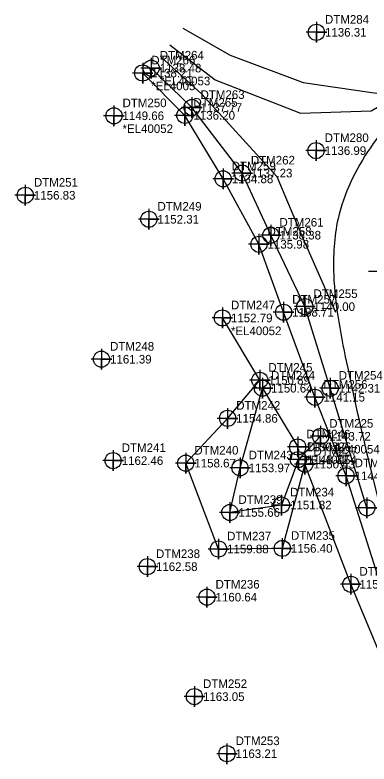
# Model space of a CAD drawing. Extents: x 1286409 to 1286829, y 857931 to 858308.
# Drawn here: x 1286408.7 to 1286511.7, y 857930.6 to 858148.3 of the extents above; entities that cross this region are included whole.
import ezdxf

# ---------------------------------------------------------------- set-up
doc = ezdxf.new("R2010")
doc.units = 0
for name, color, linetype in [('Exist DTM Breakline', 7, 'Continuous'), ('Exist DTM Breakline Cogo Comment', 7, 'Continuous'), ('Exist DTM Breakline Cogo Elevation', 7, 'Continuous'), ('Exist DTM Breakline Cogo Number', 7, 'Continuous'), ('Exist DTM Breakline Cogo Point CELL', 7, 'Continuous'), ('Exist DTM Crownline Cogo Point CELL', 7, 'Continuous'), ('Exist DTM Regular Point CELL', 7, 'Continuous'), ('Exist DTM Regular Point Cogo Elevation', 7, 'Continuous'), ('Exist DTM Regular Point Cogo Number', 7, 'Continuous'), ('Exist Roads EOP', 7, 'Continuous'), ('Exist Roads EOP Other', 7, 'Continuous'), ('Exist Roads Soil', 7, 'Continuous')]:
    doc.layers.add(name, color=color, linetype=linetype)

msp = doc.modelspace()

# ---------------------------------------------------------------- linework, layer by layer
at = {"layer": 'Exist DTM Breakline'}
for points in [[(1286520.872, 857956.475), (1286514.938, 857983.192), (1286504.975, 858014.397), (1286495.914, 858037.226), (1286486.828, 858061.942), (1286479.65, 858081.695), (1286469.24, 858100.695), (1286458.123, 858119.163), (1286445.852, 858131.468)], [(1286511.023, 858005.106), (1286500.357, 858039.834), (1286493.011, 858063.572), (1286483.119, 858084.338), (1286474.799, 858102.385), (1286460.172, 858121.45), (1286448.323, 858132.894)], [(1286517.862, 857955.312), (1286506.377, 857982.872), (1286493.003, 858017.794), (1286486.448, 857993.306), (1286467.899, 857993.131), (1286458.369, 858018.086), (1286470.547, 858031.105), (1286479.897, 858042.174), (1286469.015, 858060.288)], [(1286497.591, 858025.882), (1286491.129, 858019.112), (1286486.211, 858005.912), (1286471.196, 858003.751), (1286474.165, 858016.705), (1286480.661, 858039.856), (1286490.919, 858022.783)]]:
    msp.add_lwpolyline(points, dxfattribs=at)
at = {"layer": 'Exist DTM Breakline Cogo Point CELL'}
for points in [[(1286448.323, 858135.894), (1286448.323, 858129.894), (1286448.323, 858132.894), (1286451.323, 858132.894), (1286445.323, 858132.894)], [(1286445.852, 858134.468), (1286445.852, 858128.468), (1286445.852, 858131.468), (1286448.852, 858131.468), (1286442.852, 858131.468)], [(1286460.172, 858124.45), (1286460.172, 858118.45), (1286460.172, 858121.45), (1286463.172, 858121.45), (1286457.172, 858121.45)], [(1286437.488, 858122.042), (1286437.488, 858116.042), (1286437.488, 858119.042), (1286440.488, 858119.042), (1286434.488, 858119.042)], [(1286458.123, 858122.163), (1286458.123, 858116.163), (1286458.123, 858119.163), (1286461.123, 858119.163), (1286455.123, 858119.163)], [(1286474.799, 858105.385), (1286474.799, 858099.385), (1286474.799, 858102.385), (1286477.799, 858102.385), (1286471.799, 858102.385)], [(1286469.24, 858103.695), (1286469.24, 858097.695), (1286469.24, 858100.695), (1286472.24, 858100.695), (1286466.24, 858100.695)], [(1286447.653, 858091.967), (1286447.653, 858085.967), (1286447.653, 858088.967), (1286450.653, 858088.967), (1286444.653, 858088.967)], [(1286483.119, 858087.338), (1286483.119, 858081.338), (1286483.119, 858084.338), (1286486.119, 858084.338), (1286480.119, 858084.338)], [(1286479.65, 858084.695), (1286479.65, 858078.695), (1286479.65, 858081.695), (1286482.65, 858081.695), (1286476.65, 858081.695)], [(1286493.011, 858066.572), (1286493.011, 858060.572), (1286493.011, 858063.572), (1286496.011, 858063.572), (1286490.011, 858063.572)], [(1286486.828, 858064.942), (1286486.828, 858058.942), (1286486.828, 858061.942), (1286489.828, 858061.942), (1286483.828, 858061.942)], [(1286469.015, 858063.288), (1286469.015, 858057.288), (1286469.015, 858060.288), (1286472.015, 858060.288), (1286466.015, 858060.288)], [(1286479.897, 858045.174), (1286479.897, 858039.174), (1286479.897, 858042.174), (1286482.897, 858042.174), (1286476.897, 858042.174)], [(1286480.661, 858042.856), (1286480.661, 858036.856), (1286480.661, 858039.856), (1286483.661, 858039.856), (1286477.661, 858039.856)], [(1286500.357, 858042.834), (1286500.357, 858036.834), (1286500.357, 858039.834), (1286503.357, 858039.834), (1286497.357, 858039.834)], [(1286495.914, 858040.226), (1286495.914, 858034.226), (1286495.914, 858037.226), (1286498.914, 858037.226), (1286492.914, 858037.226)], [(1286470.547, 858034.105), (1286470.547, 858028.105), (1286470.547, 858031.105), (1286473.547, 858031.105), (1286467.547, 858031.105)], [(1286497.591, 858028.882), (1286497.591, 858022.882), (1286497.591, 858025.882), (1286500.591, 858025.882), (1286494.591, 858025.882)], [(1286490.919, 858025.783), (1286490.919, 858019.783), (1286490.919, 858022.783), (1286493.919, 858022.783), (1286487.919, 858022.783)], [(1286458.369, 858021.086), (1286458.369, 858015.086), (1286458.369, 858018.086), (1286461.369, 858018.086), (1286455.369, 858018.086)], [(1286491.129, 858022.112), (1286491.129, 858016.112), (1286491.129, 858019.112), (1286494.129, 858019.112), (1286488.129, 858019.112)], [(1286493.003, 858020.794), (1286493.003, 858014.794), (1286493.003, 858017.794), (1286496.003, 858017.794), (1286490.003, 858017.794)], [(1286474.165, 858019.705), (1286474.165, 858013.705), (1286474.165, 858016.705), (1286477.165, 858016.705), (1286471.165, 858016.705)], [(1286504.975, 858017.397), (1286504.975, 858011.397), (1286504.975, 858014.397), (1286507.975, 858014.397), (1286501.975, 858014.397)], [(1286486.211, 858008.912), (1286486.211, 858002.912), (1286486.211, 858005.912), (1286489.211, 858005.912), (1286483.211, 858005.912)], [(1286511.023, 858008.106), (1286511.023, 858002.106), (1286511.023, 858005.106), (1286514.023, 858005.106), (1286508.023, 858005.106)], [(1286471.196, 858006.751), (1286471.196, 858000.751), (1286471.196, 858003.751), (1286474.196, 858003.751), (1286468.196, 858003.751)], [(1286486.448, 857996.306), (1286486.448, 857990.306), (1286486.448, 857993.306), (1286489.448, 857993.306), (1286483.448, 857993.306)], [(1286467.899, 857996.131), (1286467.899, 857990.131), (1286467.899, 857993.131), (1286470.899, 857993.131), (1286464.899, 857993.131)], [(1286506.377, 857985.872), (1286506.377, 857979.872), (1286506.377, 857982.872), (1286509.377, 857982.872), (1286503.377, 857982.872)]]:
    msp.add_lwpolyline(points, dxfattribs=at)
for centre in [(1286445.852, 858131.468), (1286448.323, 858132.894), (1286460.172, 858121.45), (1286437.488, 858119.042), (1286458.123, 858119.163), (1286469.24, 858100.695), (1286474.799, 858102.385), (1286447.653, 858088.967), (1286483.119, 858084.338), (1286479.65, 858081.695), (1286493.011, 858063.572), (1286486.828, 858061.942), (1286469.015, 858060.288), (1286479.897, 858042.174), (1286480.661, 858039.856), (1286500.357, 858039.834), (1286495.914, 858037.226), (1286470.547, 858031.105), (1286497.591, 858025.882), (1286490.919, 858022.783), (1286458.369, 858018.086), (1286491.129, 858019.112), (1286474.165, 858016.705), (1286493.003, 858017.794), (1286504.975, 858014.397), (1286486.211, 858005.912), (1286511.023, 858005.106), (1286471.196, 858003.751), (1286467.899, 857993.131), (1286486.448, 857993.306), (1286506.377, 857982.872)]:
    msp.add_circle(centre, 2.344, dxfattribs=at)
at = {"layer": 'Exist DTM Crownline Cogo Point CELL'}
msp.add_lwpolyline([(1286514.506, 858076.789), (1286514.506, 858070.789), (1286514.506, 858073.789), (1286517.506, 858073.789), (1286511.506, 858073.789)], dxfattribs=at)
at = {"layer": 'Exist DTM Regular Point CELL'}
for points in [[(1286496.358, 858146.298), (1286496.358, 858140.298), (1286496.358, 858143.298), (1286499.358, 858143.298), (1286493.358, 858143.298)], [(1286496.256, 858111.914), (1286496.256, 858105.914), (1286496.256, 858108.914), (1286499.256, 858108.914), (1286493.256, 858108.914)], [(1286411.723, 858098.932), (1286411.723, 858092.932), (1286411.723, 858095.932), (1286414.723, 858095.932), (1286408.723, 858095.932)], [(1286433.866, 858051.289), (1286433.866, 858045.289), (1286433.866, 858048.289), (1286436.866, 858048.289), (1286430.866, 858048.289)], [(1286437.253, 858021.812), (1286437.253, 858015.812), (1286437.253, 858018.812), (1286440.253, 858018.812), (1286434.253, 858018.812)], [(1286447.217, 857991.003), (1286447.217, 857985.003), (1286447.217, 857988.003), (1286450.217, 857988.003), (1286444.217, 857988.003)], [(1286464.539, 857982.132), (1286464.539, 857976.132), (1286464.539, 857979.132), (1286467.539, 857979.132), (1286461.539, 857979.132)], [(1286460.892, 857953.227), (1286460.892, 857947.227), (1286460.892, 857950.227), (1286463.892, 857950.227), (1286457.892, 857950.227)], [(1286470.365, 857936.641), (1286470.365, 857930.641), (1286470.365, 857933.641), (1286473.365, 857933.641), (1286467.365, 857933.641)]]:
    msp.add_lwpolyline(points, dxfattribs=at)
for centre in [(1286496.358, 858143.298), (1286496.256, 858108.914), (1286411.723, 858095.932), (1286433.866, 858048.289), (1286437.253, 858018.812), (1286447.217, 857988.003), (1286464.539, 857979.132), (1286460.892, 857950.227), (1286470.365, 857933.641)]:
    msp.add_circle(centre, 2.344, dxfattribs=at)
at = {"layer": 'Exist Roads EOP'}
msp.add_spline([(1286554.506, 858138.221), (1286544.419, 858134.401), (1286528.832, 858126.933), (1286512.047, 858109.768), (1286502.652, 858089.088), (1286501.393, 858072.897), (1286505.471, 858045.649), (1286512.056, 858016.522), (1286519.805, 857984.681), (1286525.58, 857958.7)], degree=3, dxfattribs=at)
at = {"layer": 'Exist Roads EOP Other'}
for points in [[(1286457.489, 858144.476), (1286471.264, 858136.623), (1286492.557, 858128.739), (1286511.821, 858125.921), (1286519.606, 858124.807)], [(1286453.703, 858139.674), (1286466.954, 858129.445), (1286491.774, 858119.764), (1286512.279, 858120.499), (1286519.676, 858124.715)]]:
    msp.add_lwpolyline(points, dxfattribs=at)
at = {"layer": 'Exist Roads Soil'}
msp.add_lwpolyline([(1286451.264, 858136.048), (1286463.084, 858125.359), (1286484.836, 858101.378), (1286492.165, 858084.188), (1286501.894, 858062.005)], dxfattribs=at)

# ---------------------------------------------------------------- texts
at = {"layer": 'Exist DTM Breakline Cogo Comment'}
for s, p in [('*EL40053', (1286450.823, 858127.894)), ('*EL4005', (1286448.352, 858126.468)), ('*EL40052', (1286439.988, 858114.042)), ('*EL40052', (1286471.515, 858055.288)), ('*BL40054', (1286500.091, 858020.882)), ('*EL40054', (1286493.419, 858017.783))]:
    msp.add_text(s, height=2.5, dxfattribs=at).set_placement(p)
at = {"layer": 'Exist DTM Breakline Cogo Elevation'}
for s, p in [('1138.48', (1286450.823, 858131.644)), ('1138.21', (1286448.352, 858130.218)), ('1137.77', (1286462.672, 858120.2)), ('1149.66', (1286439.988, 858117.792)), ('1136.20', (1286460.623, 858117.913)), ('1137.23', (1286477.299, 858101.135)), ('1134.88', (1286471.74, 858099.445)), ('1152.31', (1286450.153, 858087.717)), ('1138.38', (1286485.619, 858083.088)), ('1135.98', (1286482.15, 858080.445)), ('1140.00', (1286495.511, 858062.322)), ('1152.79', (1286471.515, 858059.038)), ('1138.71', (1286489.328, 858060.692)), ('1150.89', (1286482.397, 858040.924)), ('1150.64', (1286483.161, 858038.606)), ('1142.31', (1286502.857, 858038.584)), ('1141.15', (1286498.414, 858035.976)), ('1154.86', (1286473.047, 858029.855)), ('1143.72', (1286500.091, 858024.632)), ('1150.17', (1286493.419, 858021.533)), ('1148.32', (1286493.629, 858017.862)), ('1158.67', (1286460.869, 858016.836)), ('1153.97', (1286476.665, 858015.455)), ('1150.43', (1286495.503, 858016.544)), ('1144.38', (1286507.475, 858013.147)), ('1151.82', (1286488.711, 858004.662)), ('1155.66', (1286473.696, 858002.501)), ('1159.88', (1286470.399, 857991.881)), ('1156.40', (1286488.948, 857992.056)), ('1154.95', (1286508.877, 857981.622))]:
    msp.add_text(s, height=2.5, dxfattribs=at).set_placement(p)
at = {"layer": 'Exist DTM Breakline Cogo Number'}
for s, p in [('DTM264', (1286450.823, 858135.394)), ('DTM266', (1286448.352, 858133.968)), ('DTM263', (1286462.672, 858123.95)), ('DTM250', (1286439.988, 858121.542)), ('DTM265', (1286460.623, 858121.663)), ('DTM262', (1286477.299, 858104.885)), ('DTM259', (1286471.74, 858103.195)), ('DTM249', (1286450.153, 858091.467)), ('DTM261', (1286485.619, 858086.838)), ('DTM258', (1286482.15, 858084.195)), ('DTM255', (1286495.511, 858066.072)), ('DTM257', (1286489.328, 858064.442)), ('DTM247', (1286471.515, 858062.788)), ('DTM245', (1286482.397, 858044.674)), ('DTM244', (1286483.161, 858042.356)), ('DTM254', (1286502.857, 858042.334)), ('DTM256', (1286498.414, 858039.726)), ('DTM242', (1286473.047, 858033.605)), ('DTM225', (1286500.091, 858028.382)), ('DTM246', (1286493.419, 858025.283)), ('DTM240', (1286460.869, 858020.586)), ('DTM226', (1286493.629, 858021.612)), ('DTM227', (1286495.503, 858020.294)), ('DTM243', (1286476.665, 858019.205)), ('DTM223', (1286507.475, 858016.897)), ('DTM234', (1286488.711, 858008.412)), ('DTM239', (1286473.696, 858006.251)), ('DTM237', (1286470.399, 857995.631)), ('DTM235', (1286488.948, 857995.806)), ('DTM219', (1286508.877, 857985.372))]:
    msp.add_text(s, height=2.5, dxfattribs=at).set_placement(p)
at = {"layer": 'Exist DTM Regular Point Cogo Elevation'}
for s, p in [('1136.31', (1286498.858, 858142.048)), ('1136.99', (1286498.756, 858107.664)), ('1156.83', (1286414.223, 858094.682)), ('1161.39', (1286436.366, 858047.039)), ('1162.46', (1286439.753, 858017.562)), ('1162.58', (1286449.717, 857986.753)), ('1160.64', (1286467.039, 857977.882)), ('1163.05', (1286463.392, 857948.977)), ('1163.21', (1286472.865, 857932.391))]:
    msp.add_text(s, height=2.5, dxfattribs=at).set_placement(p)
at = {"layer": 'Exist DTM Regular Point Cogo Number'}
for s, p in [('DTM284', (1286498.858, 858145.798)), ('DTM280', (1286498.756, 858111.414)), ('DTM251', (1286414.223, 858098.432)), ('DTM248', (1286436.366, 858050.789)), ('DTM241', (1286439.753, 858021.312)), ('DTM238', (1286449.717, 857990.503)), ('DTM236', (1286467.039, 857981.632)), ('DTM252', (1286463.392, 857952.727)), ('DTM253', (1286472.865, 857936.141))]:
    msp.add_text(s, height=2.5, dxfattribs=at).set_placement(p)

doc.saveas('drawing.dxf')
